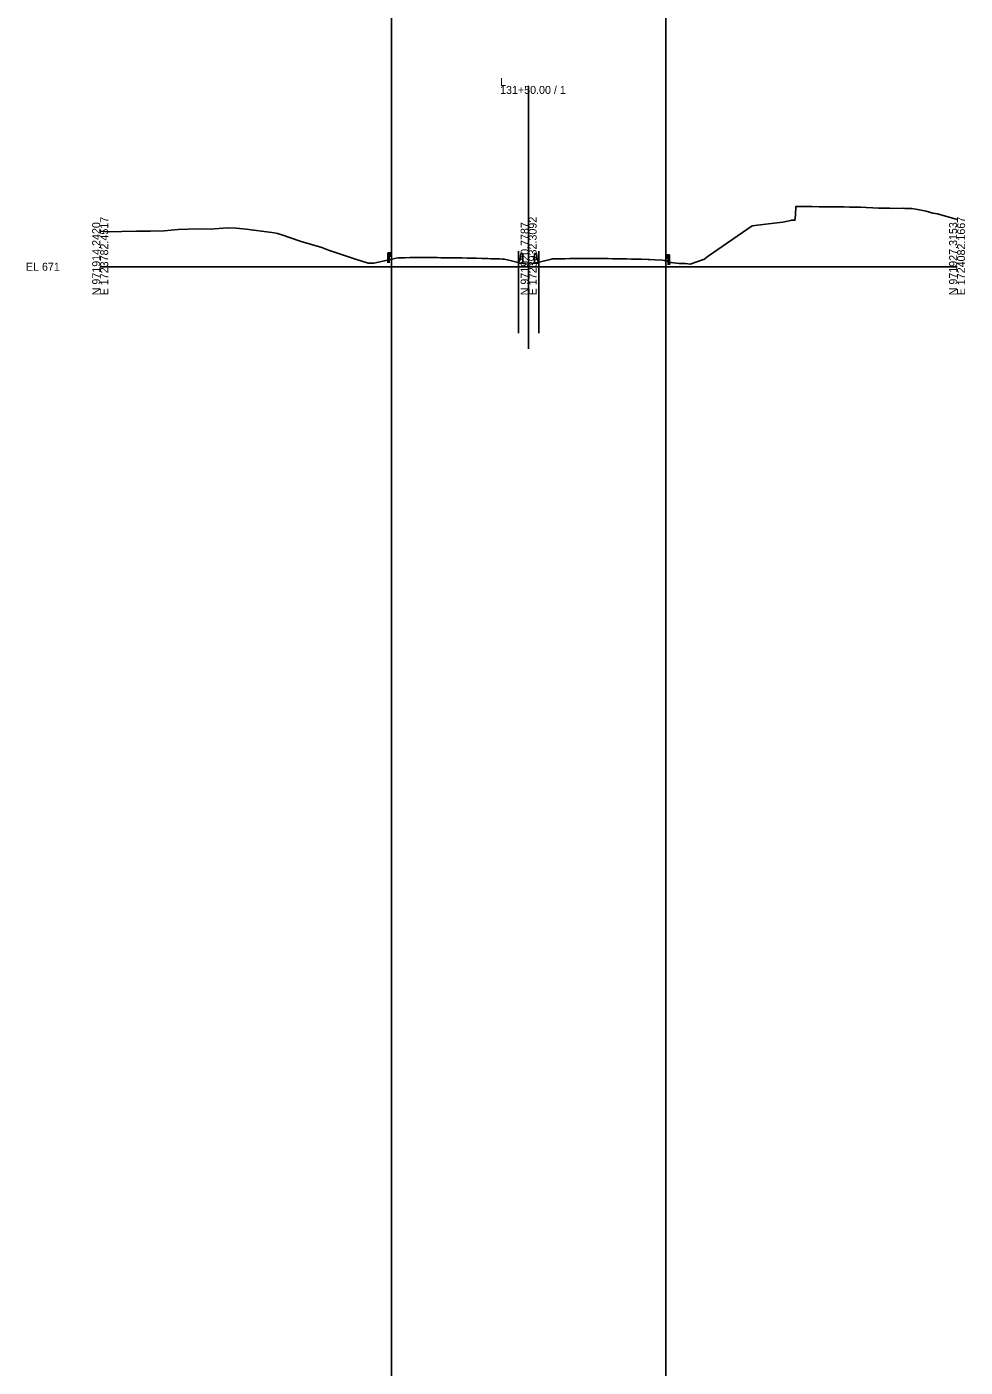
# Model space of a CAD drawing. Extents: x -26 to 303, y -29 to 15026.
# Drawn here: x -25.7 to 302.8, y 4115 to 4583.9 of the extents above; entities that cross this region are included whole.
import ezdxf

# ---------------------------------------------------------------- set-up
doc = ezdxf.new("R2010")
doc.units = 0
for name, color, linetype in [('Exist Cross Section Cell', 7, 'Continuous'), ('Exist XS Center Line Elevation Label', 7, 'Continuous'), ('Exist XS Ground Line', 7, 'Continuous'), ('Scratch_Level_0', 7, 'Continuous'), ('Typical Guardrail CELL', 7, 'Continuous'), ('Typical Median Barrier CELL', 7, 'Continuous')]:
    doc.layers.add(name, color=color, linetype=linetype)

msp = doc.modelspace()

# ---------------------------------------------------------------- linework, layer by layer
at = {"layer": 'Exist Cross Section Cell'}
for p, q in [((150, 4500), (150, 4563.26)), ((0, 4500), (150, 4500)), ((150, 4500), (300, 4500))]:
    msp.add_line(p, q, dxfattribs=at)
at = {"layer": 'Exist XS Ground Line'}
msp.add_lwpolyline([(0, 4512.4), (3.18, 4512.23), (7.57, 4512.31), (12.77, 4512.45), (17.58, 4512.44), (22.37, 4512.6), (27.27, 4512.98), (34.16, 4513.21), (38.53, 4513.17), (44.63, 4513.58), (47.6, 4513.48), (51.14, 4513.12), (60.12, 4511.96), (61.59, 4511.74), (62.13, 4511.68), (62.48, 4511.57), (63.21, 4511.28), (70.32, 4508.82), (77.63, 4506.73), (79.91, 4505.78), (87.64, 4503.22), (89.07, 4502.77), (93.87, 4501.3), (95.77, 4501.26), (100.63, 4502.35), (103.63, 4503.03), (104.38, 4503.06), (105.04, 4503.08), (106.76, 4503.15), (108.44, 4503.18), (109.26, 4503.19), (110.41, 4503.2), (111.23, 4503.21), (111.77, 4503.2), (112.8, 4503.2), (114.27, 4503.19), (115.63, 4503.19), (116.77, 4503.19), (118.04, 4503.18), (119.26, 4503.17), (120.6, 4503.15), (121.75, 4503.14), (122.51, 4503.13), (123.05, 4503.13), (123.61, 4503.13), (124.24, 4503.12), (125.83, 4503.09), (126.74, 4503.07), (128.47, 4503.03), (129.25, 4503.02), (129.98, 4503), (131.76, 4502.95), (133.67, 4502.9), (134.25, 4502.88), (134.69, 4502.87), (135.75, 4502.84), (136.77, 4502.8), (137.16, 4502.79), (139.27, 4502.74), (139.81, 4502.72), (140.86, 4502.69), (141.46, 4502.67), (143.55, 4502.13), (147.27, 4501.2), (148.75, 4501.06), (149.84, 4500.86), (150.95, 4501), (152.17, 4501.23), (157.54, 4502.52), (158.39, 4502.72), (159.29, 4502.74), (159.88, 4502.75), (161.75, 4502.8), (162.63, 4502.82), (164.48, 4502.87), (165.91, 4502.86), (166.83, 4502.86), (168.37, 4502.86), (169.32, 4502.87), (170.79, 4502.87), (171.82, 4502.87), (173.19, 4502.87), (174.33, 4502.87), (175.58, 4502.87), (176.82, 4502.86), (177.28, 4502.86), (177.85, 4502.85), (179.32, 4502.82), (180.79, 4502.79), (181.8, 4502.77), (182.73, 4502.75), (184.31, 4502.72), (186.01, 4502.68), (186.8, 4502.66), (189.06, 4502.61), (189.47, 4502.6), (191.82, 4502.5), (192.32, 4502.48), (194.32, 4502.39), (196.85, 4502.26), (197.43, 4502.24), (197.86, 4502.23), (197.97, 4502.12), (198.42, 4502.05), (198.83, 4501.82), (199.73, 4501.54), (202.66, 4501.08), (204.9, 4501.08), (206.53, 4500.85), (210.9, 4502.41), (211.3, 4502.59), (212.89, 4503.7), (228.21, 4514.3), (236.91, 4515.35), (239.01, 4515.6), (241.77, 4516.2), (241.87, 4516.29), (243.21, 4516.27), (243.46, 4518.1), (243.57, 4521.08), (244.16, 4521.09), (244.47, 4521.08), (246.83, 4521.07), (249.23, 4521.05), (251.68, 4521.01), (254.24, 4521), (256.65, 4520.98), (257.37, 4520.97), (257.7, 4520.97), (258.19, 4520.97), (259.31, 4520.95), (260.51, 4520.92), (262.37, 4520.88), (263.01, 4520.88), (266.25, 4520.82), (268.16, 4520.69), (270.47, 4520.62), (272.44, 4520.54), (274.12, 4520.49), (276.41, 4520.46), (277.54, 4520.42), (281.22, 4520.44), (281.66, 4520.43), (284.08, 4520.41), (285.58, 4520.09), (289.14, 4519.41), (291.47, 4518.74), (293.11, 4518.5), (300, 4516.48)], dxfattribs=at)
at = {"layer": 'Scratch_Level_0'}
for p, q in [((102, 15009.56), (102, -28.7)), ((198, 15009.56), (198, -28.7)), ((146.46, 4505.5), (146.46, 4476.8)), ((153.54, 4505.5), (153.54, 4476.8)), ((150, 4500), (150, 4471.3)), ((150, 4500), (150, 4471.3))]:
    msp.add_line(p, q, dxfattribs=at)
at = {"layer": 'Typical Guardrail CELL'}
for p, q in [((101.18, 4504.85), (100.68, 4504.85)), ((100.68, 4504.85), (100.68, 4502.36)), ((101.18, 4502.36), (100.68, 4502.36)), ((100.68, 4502.36), (100.68, 4501.35)), ((101.18, 4504.85), (101.18, 4502.36)), ((101.18, 4504.85), (101.68, 4504.85)), ((101.18, 4503.69), (101.68, 4503.69)), ((101.18, 4502.36), (101.18, 4501.35)), ((101.68, 4504.85), (101.68, 4503.69)), ((101.68, 4504.85), (101.97, 4504.64)), ((101.68, 4504.31), (101.97, 4504.52)), ((101.68, 4504.27), (101.68, 4504.31)), ((101.68, 4504.27), (101.68, 4504.22)), ((101.68, 4504.22), (101.97, 4504.02)), ((101.68, 4503.69), (101.97, 4503.89)), ((198.32, 4504.15), (198.03, 4503.95)), ((198.32, 4503.62), (198.03, 4503.82)), ((198.32, 4503.53), (198.03, 4503.32)), ((198.32, 4502.99), (198.03, 4503.2)), ((198.82, 4504.15), (198.32, 4504.15)), ((198.32, 4504.15), (198.32, 4502.99)), ((198.32, 4503.57), (198.32, 4503.62)), ((198.32, 4503.57), (198.32, 4503.53)), ((198.82, 4502.99), (198.32, 4502.99)), ((198.82, 4504.15), (198.82, 4501.67)), ((198.82, 4504.15), (199.32, 4504.15)), ((199.32, 4504.15), (199.32, 4501.67)), ((198.82, 4501.67), (199.32, 4501.67)), ((198.82, 4501.67), (198.82, 4500.66)), ((199.32, 4501.67), (199.32, 4500.66))]:
    msp.add_line(p, q, dxfattribs=at)
for centre, start, end in [((101.92, 4504.58), 304.9888, 54.997), ((101.92, 4503.95), 304.9634, 54.9941), ((198.08, 4503.89), 125.003, 235.0112), ((198.08, 4503.26), 125.0059, 235.0366)]:
    msp.add_arc(centre, 0.0776, start, end, dxfattribs=at)
at = {"layer": 'Typical Median Barrier CELL'}
for p, q in [((146.46, 4501.63), (146.92, 4502.29)), ((147.07, 4502.68), (147.29, 4504.63)), ((147.29, 4504.63), (147.96, 4504.63)), ((147.96, 4504.63), (147.96, 4501.21)), ((152.71, 4504.63), (152.04, 4504.63)), ((152.04, 4504.63), (152.04, 4501.21)), ((152.93, 4502.68), (152.71, 4504.63)), ((153.54, 4501.63), (153.08, 4502.29)), ((146.46, 4501.21), (146.46, 4501.63)), ((147.96, 4501.21), (146.46, 4501.21)), ((152.04, 4501.21), (153.54, 4501.21)), ((153.54, 4501.21), (153.54, 4501.63))]:
    msp.add_line(p, q, dxfattribs=at)
for centre, start, end in [((146.24, 4502.76), 325.0039, 353.9447), ((153.76, 4502.76), 186.0553, 214.9961)]:
    msp.add_arc(centre, 0.833, start, end, dxfattribs=at)

# ---------------------------------------------------------------- texts
at = {"layer": 'Exist Cross Section Cell'}
for s, p in [('131+50.00 / 1', (140, 4560.46)), ('L', (140, 4563.26)), ('EL 671', (-26, 4498.6))]:
    msp.add_text(s, height=2.8, dxfattribs=at).set_placement(p)
for s, p in [('E 1723782.4517', (2.8, 4490)), ('E 1723932.3092', (152.8, 4490)), ('E 1724082.1667', (302.8, 4490)), ('N 971914.2420', (0, 4490)), ('N 971920.7787', (150, 4490)), ('N 971927.3153', (300, 4490))]:
    msp.add_text(s, height=2.8, rotation=90, dxfattribs=at).set_placement(p)
at = {"layer": 'Exist XS Center Line Elevation Label'}
msp.add_text('671.88', height=0.18, dxfattribs=at).set_placement((149.64, 4500.39))

doc.saveas('drawing.dxf')
